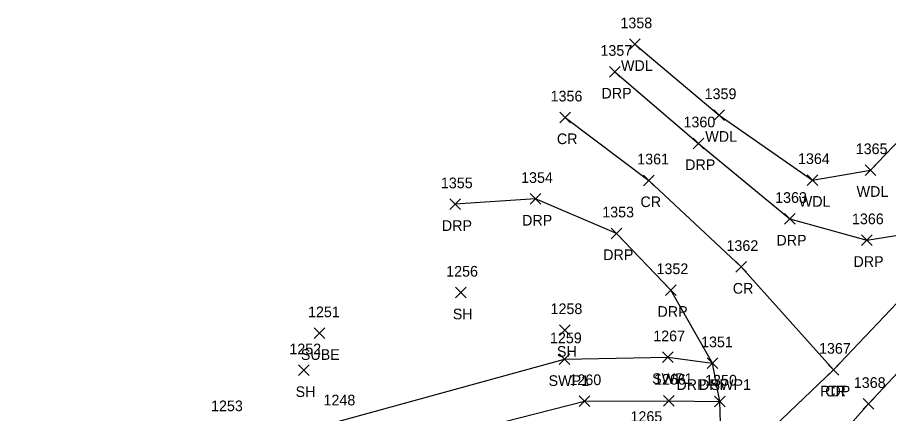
# Model space of a CAD drawing. Extents: x 1586965 to 1590952, y 716317 to 720029.
# Drawn here: x 1587644.2 to 1587807.3, y 719954.3 to 720028.5 of the extents above; entities that cross this region are included whole.
import ezdxf

# ---------------------------------------------------------------- set-up
doc = ezdxf.new("R2010")
doc.units = 0
for name, color, linetype in [('L_A', 7, 'Continuous'), ('L_I', 7, 'Continuous'), ('L_TIC', 7, 'Continuous'), ('LAWA', 7, 'Continuous'), ('P_A', 7, 'Continuous'), ('P_I', 7, 'Continuous'), ('P_TIC', 7, 'Continuous'), ('PET', 7, 'Continuous'), ('PRC', 7, 'Continuous'), ('R_A', 7, 'Continuous'), ('R_I', 7, 'Continuous'), ('R_TIC', 7, 'Continuous'), ('RDP', 7, 'Continuous'), ('RSW', 7, 'Continuous'), ('U_A', 7, 'Continuous'), ('U_I', 7, 'Continuous'), ('U_TIC', 7, 'Continuous')]:
    doc.layers.add(name, color=color, linetype=linetype)

msp = doc.modelspace()

# ---------------------------------------------------------------- linework, layer by layer
at = {"layer": 'L_TIC'}
for points in [[(1587758.78, 720022.49), (1587760.78, 720024.49)], [(1587760.78, 720022.49), (1587758.78, 720024.49)], [(1587774.56, 720009.22), (1587776.56, 720011.22)], [(1587776.56, 720009.22), (1587774.56, 720011.22)], [(1587802.89, 719998.91), (1587804.89, 720000.91)], [(1587804.89, 719998.91), (1587802.89, 720000.91)], [(1587792.08, 719997.06), (1587794.08, 719999.06)], [(1587794.08, 719997.06), (1587792.08, 719999.06)], [(1587726.21, 719975.96), (1587728.21, 719977.96)], [(1587728.21, 719975.96), (1587726.21, 719977.96)], [(1587745.7, 719968.94), (1587747.7, 719970.94)], [(1587747.7, 719968.94), (1587745.7, 719970.94)], [(1587696.79, 719961.41), (1587698.79, 719963.41)], [(1587698.79, 719961.41), (1587696.79, 719963.41)]]:
    msp.add_lwpolyline(points, dxfattribs=at)
at = {"layer": 'LAWA'}
msp.add_lwpolyline([(1587759.78, 720023.49), (1587775.56, 720010.22), (1587793.08, 719998.06), (1587803.89, 719999.91), (1587823.3, 720020.21)], dxfattribs=at)
at = {"layer": 'P_TIC'}
for points in [[(1587745.77, 720008.78), (1587747.77, 720010.78)], [(1587747.77, 720008.78), (1587745.77, 720010.78)], [(1587761.41, 719996.99), (1587763.41, 719998.99)], [(1587763.41, 719996.99), (1587761.41, 719998.99)], [(1587778.69, 719980.77), (1587780.69, 719982.77)], [(1587780.69, 719980.77), (1587778.69, 719982.77)], [(1587796.01, 719961.52), (1587798.01, 719963.52)], [(1587798.01, 719961.52), (1587796.01, 719963.52)], [(1587796.01, 719961.52), (1587798.01, 719963.52)], [(1587798.01, 719961.52), (1587796.01, 719963.52)], [(1587802.53, 719955.11), (1587804.53, 719957.11)], [(1587804.53, 719955.11), (1587802.53, 719957.11)]]:
    msp.add_lwpolyline(points, dxfattribs=at)
at = {"layer": 'PET'}
msp.add_lwpolyline([(1587685.91, 719854.02), (1587701.42, 719870.84), (1587715.13, 719880.1), (1587736.18, 719901.89), (1587760.55, 719926.61), (1587776.13, 719942.57), (1587797.01, 719962.52), (1587823.07, 719989.96), (1587838.32, 720006.82)], dxfattribs=at)
at = {"layer": 'PRC'}
for points in [[(1587746.77, 720009.78), (1587762.41, 719997.99), (1587779.69, 719981.77), (1587797.01, 719962.52)], [(1587746.77, 720009.78), (1587762.41, 719997.99), (1587779.69, 719981.77), (1587797.01, 719962.52)], [(1587717.2, 719859.97), (1587724.35, 719876.95), (1587738.37, 719893.54), (1587760.76, 719912.63), (1587787.69, 719938.18), (1587803.53, 719956.11), (1587829.2, 719983.55), (1587845.42, 720001.43)], [(1587717.2, 719859.97), (1587724.35, 719876.95), (1587738.37, 719893.54), (1587760.76, 719912.63), (1587787.69, 719938.18), (1587803.53, 719956.11), (1587829.2, 719983.55), (1587845.42, 720001.43)]]:
    msp.add_lwpolyline(points, dxfattribs=at)
at = {"layer": 'R_TIC'}
for points in [[(1587755.05, 720017.33), (1587757.05, 720019.33)], [(1587757.05, 720017.33), (1587755.05, 720019.33)], [(1587770.73, 720003.93), (1587772.73, 720005.93)], [(1587772.73, 720003.93), (1587770.73, 720005.93)], [(1587740.19, 719993.52), (1587742.19, 719995.52)], [(1587742.19, 719993.52), (1587740.19, 719995.52)], [(1587725.17, 719992.52), (1587727.17, 719994.52)], [(1587727.17, 719992.52), (1587725.17, 719994.52)], [(1587787.8, 719989.78), (1587789.8, 719991.78)], [(1587789.8, 719989.78), (1587787.8, 719991.78)], [(1587755.38, 719987.06), (1587757.38, 719989.06)], [(1587757.38, 719987.06), (1587755.38, 719989.06)], [(1587802.23, 719985.78), (1587804.23, 719987.78)], [(1587804.23, 719985.78), (1587802.23, 719987.78)], [(1587765.54, 719976.43), (1587767.54, 719978.43)], [(1587767.54, 719976.43), (1587765.54, 719978.43)], [(1587745.6, 719963.48), (1587747.6, 719965.48)], [(1587747.6, 719963.48), (1587745.6, 719965.48)], [(1587764.98, 719963.85), (1587766.98, 719965.85)], [(1587766.98, 719963.85), (1587764.98, 719965.85)], [(1587773.31, 719962.73), (1587775.31, 719964.73)], [(1587775.31, 719962.73), (1587773.31, 719964.73)], [(1587773.31, 719962.73), (1587775.31, 719964.73)], [(1587775.31, 719962.73), (1587773.31, 719964.73)], [(1587749.38, 719955.64), (1587751.38, 719957.64)], [(1587751.38, 719955.64), (1587749.38, 719957.64)], [(1587765.18, 719955.72), (1587767.18, 719957.72)], [(1587767.18, 719955.72), (1587765.18, 719957.72)], [(1587774.73, 719955.55), (1587776.73, 719957.55)], [(1587776.73, 719955.55), (1587774.73, 719957.55)], [(1587774.73, 719955.55), (1587776.73, 719957.55)], [(1587776.73, 719955.55), (1587774.73, 719957.55)]]:
    msp.add_lwpolyline(points, dxfattribs=at)
at = {"layer": 'RDP'}
for points in [[(1587756.05, 720018.33), (1587771.73, 720004.93), (1587788.8, 719990.78), (1587803.23, 719986.78), (1587823.07, 719989.96)], [(1587776.13, 719942.57), (1587775.73, 719956.55), (1587774.31, 719963.73), (1587766.54, 719977.43), (1587756.38, 719988.06), (1587741.19, 719994.52), (1587726.17, 719993.52)]]:
    msp.add_lwpolyline(points, dxfattribs=at)
at = {"layer": 'RSW'}
for points in [[(1587502.47, 719906.21), (1587519.59, 719892.17), (1587545.54, 719878.27), (1587571.68, 719875.12), (1587599.39, 719889.75), (1587635.09, 719915.47), (1587660.31, 719927.61), (1587704.19, 719952.84), (1587746.6, 719964.48), (1587765.98, 719964.85), (1587774.31, 719963.73)], [(1587496.93, 719897.46), (1587515.3, 719885.59), (1587544.67, 719871.63), (1587573.67, 719867.5), (1587603.93, 719882.63), (1587638.37, 719908.04), (1587662.83, 719922.42), (1587707.8, 719945.74), (1587750.38, 719956.64), (1587766.18, 719956.72), (1587775.73, 719956.55)]]:
    msp.add_lwpolyline(points, dxfattribs=at)
at = {"layer": 'U_TIC'}
for points in [[(1587699.73, 719968.36), (1587701.73, 719970.36)], [(1587701.73, 719968.36), (1587699.73, 719970.36)]]:
    msp.add_lwpolyline(points, dxfattribs=at)

# ---------------------------------------------------------------- texts
at = {"layer": 'L_A'}
for s, p in [('WDL', (1587757.2, 720018.49)), ('WDL', (1587772.98, 720005.22)), ('WDL', (1587801.31, 719994.91)), ('WDL', (1587790.49, 719993.06)), ('SH', (1587725.7, 719971.96)), ('SH', (1587745.19, 719964.94)), ('SH', (1587696.28, 719957.41))]:
    msp.add_text(s, height=2, dxfattribs=at).set_placement(p)
at = {"layer": 'L_I'}
for s, p in [('1358', (1587757.09, 720026.49)), ('1359', (1587772.86, 720013.22)), ('1365', (1587801.15, 720002.91)), ('1364', (1587790.34, 720001.06)), ('1256', (1587724.47, 719979.96)), ('1258', (1587744.01, 719972.94)), ('1252', (1587695.1, 719965.41)), ('1253', (1587680.44, 719954.75)), ('1265', (1587758.98, 719952.74))]:
    msp.add_text(s, height=2, dxfattribs=at).set_placement(p)
at = {"layer": 'P_A'}
for s, p in [('CR', (1587745.2, 720004.78)), ('CR', (1587760.84, 719992.99)), ('CR', (1587778.12, 719976.77)), ('RDP', (1587794.49, 719957.52)), ('CR', (1587795.44, 719957.52))]:
    msp.add_text(s, height=2, dxfattribs=at).set_placement(p)
at = {"layer": 'P_I'}
for s, p in [('1356', (1587744.02, 720012.78)), ('1361', (1587760.24, 720000.99)), ('1362', (1587776.95, 719984.77)), ('1367', (1587794.27, 719965.52)), ('1367', (1587794.27, 719965.52)), ('1368', (1587800.79, 719959.11))]:
    msp.add_text(s, height=2, dxfattribs=at).set_placement(p)
at = {"layer": 'R_A'}
for s, p in [('DRP', (1587753.54, 720013.33)), ('DRP', (1587769.21, 719999.93)), ('DRP', (1587723.66, 719988.52)), ('DRP', (1587738.68, 719989.52)), ('DRP', (1587786.29, 719985.78)), ('DRP', (1587753.87, 719983.06)), ('DRP', (1587800.72, 719981.78)), ('DRP', (1587764.03, 719972.43)), ('SWP1', (1587743.64, 719959.48)), ('SWP1', (1587763.02, 719959.85)), ('DRP SWP1', (1587767.57, 719958.73)), ('DRP', (1587771.8, 719958.73))]:
    msp.add_text(s, height=2, dxfattribs=at).set_placement(p)
at = {"layer": 'R_I'}
for s, p in [('1357', (1587753.35, 720021.33)), ('1360', (1587768.9, 720007.93)), ('1355', (1587723.48, 719996.52)), ('1354', (1587738.5, 719997.52)), ('1363', (1587786.06, 719993.78)), ('1353', (1587753.69, 719991.06)), ('1366', (1587800.44, 719989.78)), ('1352', (1587763.85, 719980.43)), ('1259', (1587743.9, 719967.48)), ('1267', (1587763.24, 719967.85)), ('1351', (1587772.19, 719966.73)), ('1351', (1587772.19, 719966.73)), ('1260', (1587747.55, 719959.64)), ('1266', (1587763.38, 719959.72)), ('1350', (1587772.95, 719959.55)), ('1350', (1587772.95, 719959.55)), ('1248', (1587701.5, 719955.84))]:
    msp.add_text(s, height=2, dxfattribs=at).set_placement(p)
at = {"layer": 'U_A'}
msp.add_text('SUBE', height=2, dxfattribs=at).set_placement((1587697.26, 719964.36))
at = {"layer": 'U_I'}
msp.add_text('1251', height=2, dxfattribs=at).set_placement((1587698.6, 719972.36))

doc.saveas('drawing.dxf')
